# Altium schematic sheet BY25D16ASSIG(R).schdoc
size 127 x 101 mm
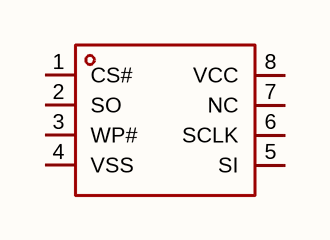
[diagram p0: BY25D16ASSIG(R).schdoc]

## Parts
U?  by25d16assig(r)  [SOP-8_L5.3-W5.3-P1.27-LS8.0-BL]  (value not drawn)

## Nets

Not connected (* = marked no-connect by the designer): U? 1(CS#) 2(SO) 3(WP#) 4(VSS) 5(SI) 6(SCLK) 7(NC) 8(VCC)

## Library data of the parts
U? = by25d16assig(r): 接口类型:SPI;存储容量:16Mbit;时钟频率(fc):108MHz;; Manufacturer: BOYAMICRO(博雅); AddInBom: yes; ModelId: e456afcfff5840a795bdd4917416584f; ModelName: SOP-8_L5.2-W5.3-H2.1-LS7.9-P1.27; ModelTransform: 311.024,204.724,0,90,0,0,0,0.0005,0; Interface: SPI; Memory Size: 16Mbit; Clock Frequency: 108MHz; Voltage - Supply: 2.7V~3.6V; Standby Supply Current: 5uA; Program / Erase Cycles: 100000次; Page Programming Time (Tpp): 700us; Block Erase Time(tBE): 300ms@(32KB); Data Retention - TDR (Year): 20年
